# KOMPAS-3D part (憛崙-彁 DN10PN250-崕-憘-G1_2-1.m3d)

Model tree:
1. Объединить компоненты:1  (labels: СЕНС-ПР DN10PN250-НО-G1/2-1)
2. Эскиз:1
3. Операция выдавливания:1
     Расстояние 1 = 14; Расстояние 2 = 14
4. Фаска:1
     Угол = 45; Длина 1 = 2; Длина 2 = 2

Referenced files in D:\Савин\!СЕНСОР\3D для заказчика\!Новый перечень\СЕНС-ПР\5. СЕНС-ПР-PN250-НО\DN10\: СЕНС-ПР DN10PN250-НО-G1_2-1.a3d
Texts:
  СЕНС-ПР DN10PN250-НО-СВ-G1/2-1
  ООО НПП Сенсор
  СЕНС-ПР DN10PN250-НО-G1/2-1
